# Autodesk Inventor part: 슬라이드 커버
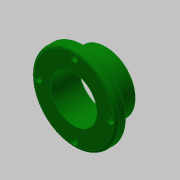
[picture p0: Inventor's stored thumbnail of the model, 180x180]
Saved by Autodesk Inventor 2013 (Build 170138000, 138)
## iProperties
Created: 2015-10
Part Number: 슬라이드 커버
Document SubType Name: Modeling
Designer: mdu
Density: 2.71 g/cm^3
Material: 알루미늄 6061
Mass: 206.361 g
Surface Area: 229.996 cm^2
Volume: 76.148 cm^3
Author: mdu
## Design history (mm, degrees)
sketch "스케치1"
  geometry: C1 r 46 at (0, -39.25) reference; C2 r 32.5 at (0, -39.25) reference; 1 further point
  node "참조1"
  node "참조2"
extrude "돌출1" new body sketch "스케치1" distance "d0" = 10; taper "d1" = 0 deg
extrude "돌출2" join sketch "스케치1" distance "d2" = 25; taper "d3" = 0 deg
hole "구멍1" diameter "d6" = 50; stored, may be unused: countersink angle "d10" = 90 deg, drill point angle "d12" = 118 deg; dims "d4" = 10, "d5" = 10, "d7" = 6, "d8" = 4, "d9" = 2, "d11" = 8
sketch "스케치2"
  geometry: C1 r 46 at (0, 0) reference; C2 r 1.621 at (0, 39) reference; C3 r 1.621 at (39, 0) reference; C4 r 1.621 at (0, -39) reference; C5 r 1.621 at (-39, 0) reference; C6 r 33.5 at (0, 0) reference; 1 further point
hole "구멍2" sketch "스케치2" at (0, 39) diameter "d13" = 4.5; stored, may be unused: countersink angle "d17" = 90 deg, drill point angle "d19" = 118 deg; dims "d14" = 6, "d15" = 8, "d16" = 4.4, "d18" = 8
fillet "모깎기1" dims "d23" = 3
chamfer "모따기1" distance "d24" = 1; stored, may be unused: second distance "d25" = 2, angle "d26" = 45 deg
sketch "스케치3"
  geometry: C1 r 25 at (0, 0); C2 r 30 at (0, 0); C3 r 26 at (0, 0) reference; 1 further point
  constraints: 2 centre point, 2 coincident
  dimensions: "d27" = 60 diameter of C2
extrude "돌출3" cut sketch "스케치3" distance "d28" = 3; taper "d29" = 0 deg
chamfer "모따기2" distance "d30" = 1; stored, may be unused: second distance "d31" = 2, angle "d32" = 45 deg
node "솔리드1"
pattern_circular "원형 패턴1" dims angle "d21" = 360 deg
node "참조3"
